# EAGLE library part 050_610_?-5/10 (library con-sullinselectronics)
.050 DIP EDGE CARD CONNECTOR .050 [1.27mm] CONTACT CENTERS .610" INSULATEOR HEIGHT Source: .050 DIP EDGE CARD.pdf
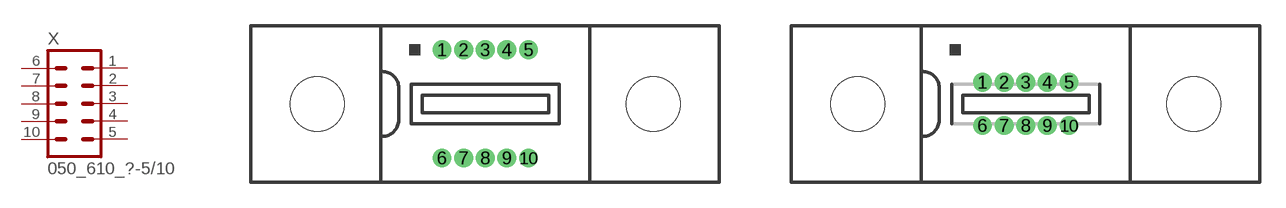
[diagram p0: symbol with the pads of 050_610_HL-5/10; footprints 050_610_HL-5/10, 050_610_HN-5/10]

Designator prefix X

## 050_610_HL-5/10 (OC_FARNELL: unknown; OC_NEWARK: unknown)  [050_610_HL-5/10]
1  1  pas
2  2  pas
3  3  pas
4  4  pas
5  5  pas
6  6  pas
7  7  pas
8  8  pas
9  9  pas
10  10  pas

## 050_610_HN-5/10 (OC_FARNELL: unknown; OC_NEWARK: unknown)  [050_610_HN-5/10]
Pads as for 050_610_HL-5/10

## 050_610_HH-5/10 (OC_FARNELL: unknown; OC_NEWARK: unknown)  [050_610_HH-5/10]
Pads as for 050_610_HL-5/10

## 050_610_HF-5/10 (OC_FARNELL: unknown; OC_NEWARK: unknown)  [050_610_HF-5/10]
Pads as for 050_610_HL-5/10

## Footprint 050_610_HL-5/10 (pad centres in mm)
.050 DIP EDGE CARD CONNECTOR DIP SOLDER .050 [1.27mm] CONTACT CENTERS .610" INSULATEOR HEIGHT Source: .050 DIP EDGE CARD.pdf
drill 0.6 pad 1 round: 1 -2.54,3.175; 2 -1.27,3.175; 3 0,3.175; 4 1.27,3.175; 5 2.54,3.175; 6 -2.54,-3.175; 7 -1.27,-3.175; 8 0,-3.175; 9 1.27,-3.175; 10 2.54,-3.175
hole 3.18 at -9.855,0
hole 3.18 at 9.855,0

## Footprint 050_610_HN-5/10 (pad centres in mm)
.050 DIP EDGE CARD CONNECTOR DIP SOLDER .050 [1.27mm] CONTACT CENTERS .610" INSULATEOR HEIGHT Source: .050 DIP EDGE CARD.pdf
drill 0.6 pad 1 round: 1 -2.54,1.27; 2 -1.27,1.27; 3 0,1.27; 4 1.27,1.27; 5 2.54,1.27; 6 -2.54,-1.27; 7 -1.27,-1.27; 8 0,-1.27; 9 1.27,-1.27; 10 2.54,-1.27
hole 3.18 at -9.855,0
hole 3.18 at 9.855,0

## Footprint 050_610_HH-5/10 (pad centres in mm)
.050 DIP EDGE CARD CONNECTOR STAGGERED DIP SOLDER .050 [1.27mm] CONTACT CENTERS .610" INSULATEOR HEIGHT Source: .050 DIP EDGE CARD.pdf
drill 0.6 pad 1 round: 1 -2.54,2.54; 2 -1.27,1.27; 3 0,2.54; 4 1.27,1.27; 5 2.54,2.54; 6 -2.54,-1.27; 7 -1.27,-2.54; 8 0,-1.27; 9 1.27,-2.54; 10 2.54,-1.27
hole 3.18 at -9.855,0
hole 3.18 at 9.855,0

## Footprint 050_610_HF-5/10 (pad centres in mm)
.050 DIP EDGE CARD CONNECTOR SURFACE MOUNT .050 [1.27mm] CONTACT CENTERS .610" INSULATEOR HEIGHT Source: .050 DIP EDGE CARD.pdf
smd 1 x 2.5: 1 -2.54,5.715; 2 -1.27,5.715; 3 0,5.715; 4 1.27,5.715; 5 2.54,5.715; 6 -2.54,-5.715; 7 -1.27,-5.715; 8 0,-5.715; 9 1.27,-5.715; 10 2.54,-5.715
hole 3.18 at -9.855,0
hole 3.18 at 9.855,0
